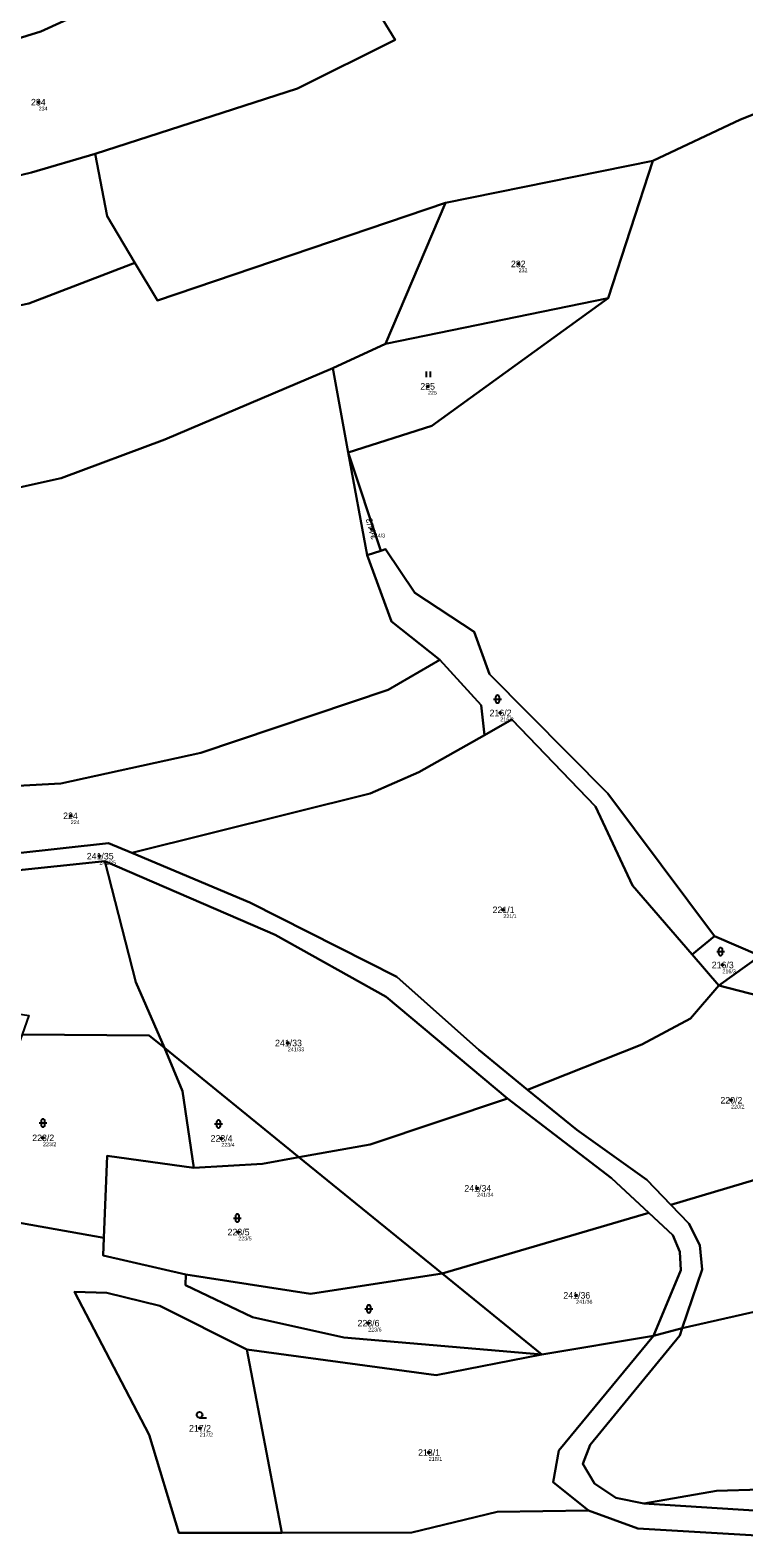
# Model space of a CAD drawing. Extents: x -766177 to -763254, y -1057727 to -1053915.
# Drawn here: x -764774.5 to -764589.7, y -1057477.4 to -1057086.8 of the extents above; entities that cross this region are included whole.
import ezdxf

# ---------------------------------------------------------------- set-up
doc = ezdxf.new("R2010")
doc.units = 0
for name, color, linetype in [('Vrstva 1', 7, 'Continuous'), ('Vrstva 2', 7, 'Continuous'), ('Vrstva 3', 7, 'Continuous'), ('Vrstva 50', 7, 'Continuous'), ('Vrstva 51', 7, 'Continuous')]:
    doc.layers.add(name, color=color, linetype=linetype)

msp = doc.modelspace()

# ---------------------------------------------------------------- linework, layer by layer
at = {"layer": 'Vrstva 1'}
for p, q in [((-764613.25, -1057120.65), (-764666.92, -1057131.53)), ((-764624.8, -1057156.25), (-764613.25, -1057120.65)), ((-764666.92, -1057131.53), (-764682.46, -1057168.07)), ((-764624.8, -1057156.25), (-764682.46, -1057168.07)), ((-764682.46, -1057168.07), (-764696.11, -1057174.39)), ((-764696.11, -1057174.39), (-764692.12, -1057196.22)), ((-764687.26, -1057222.81), (-764692.12, -1057196.22)), ((-764692.12, -1057196.22), (-764683.69, -1057221.69)), ((-764683.69, -1057221.69), (-764687.26, -1057222.81)), ((-764603.1, -1057326.29), (-764597.29, -1057321.56)), ((-764585.48, -1057326.67), (-764597.29, -1057321.56)), ((-764603.1, -1057326.29), (-764596.18, -1057334.33)), ((-764585.48, -1057326.67), (-764596.18, -1057334.33)), ((-764704.89, -1057378.8), (-764739.69, -1057350.49)), ((-764667.8, -1057408.98), (-764704.89, -1057378.8)), ((-764667.8, -1057408.98), (-764614.28, -1057393.22)), ((-764642.01, -1057429.97), (-764667.8, -1057408.98)), ((-764613.07, -1057425.08), (-764605.63, -1057423.15)), ((-764613.07, -1057425.08), (-764642.01, -1057429.97)), ((-764709.36, -1057476.11), (-764718.38, -1057428.64))]:
    msp.add_line(p, q, dxfattribs=at)
for points in [[(-764708.9, -1057047.43), (-764739.3, -1057069.37), (-764754.19, -1057078.72), (-764760.91, -1057082.25), (-764771.73, -1057087.14), (-764793.82, -1057093.95), (-764861.05, -1057109.51)], [(-764757.64, -1057118.88), (-764705.22, -1057101.91), (-764679.94, -1057089.32), (-764690.54, -1057072), (-764708.9, -1057047.43)], [(-764613.25, -1057120.65), (-764590.56, -1057109.9), (-764567.9, -1057100.88), (-764530.4, -1057087.58), (-764523, -1057086.68)], [(-764757.64, -1057118.88), (-764774.17, -1057123.68), (-764802.92, -1057130.57), (-764851.9, -1057136.58), (-764858.21, -1057124.08), (-764860.35, -1057113.34)], [(-764747.36, -1057147.07), (-764754.56, -1057134.97), (-764757.64, -1057118.88)], [(-764747.36, -1057147.07), (-764741.54, -1057156.84), (-764666.92, -1057131.53)], [(-764870.84, -1057163.2), (-764870.68, -1057169.13), (-764851.02, -1057169.28), (-764804.04, -1057163.72), (-764774.82, -1057157.64), (-764747.36, -1057147.07)], [(-764692.12, -1057196.22), (-764670.45, -1057189.31), (-764624.8, -1057156.25)], [(-764869.55, -1057216.04), (-764830.16, -1057214.01), (-764788.75, -1057207.77), (-764766.49, -1057202.85), (-764739.57, -1057192.87), (-764696.11, -1057174.39)], [(-764687.26, -1057222.81), (-764680.88, -1057240.01), (-764668.44, -1057249.98)], [(-764597.29, -1057321.56), (-764624.95, -1057284.61), (-764655.55, -1057253.65), (-764659.55, -1057242.65), (-764674.9, -1057232.59), (-764682.46, -1057221.3), (-764683.69, -1057221.69)], [(-764668.44, -1057249.98), (-764681.75, -1057257.76), (-764730.25, -1057274.03), (-764766.5, -1057282), (-764809.8, -1057284.32), (-764867.31, -1057280.02)], [(-764668.44, -1057249.98), (-764657.71, -1057261.73), (-764656.87, -1057269.44)], [(-764656.87, -1057269.44), (-764649.81, -1057265.44), (-764628.07, -1057287.93), (-764618.51, -1057308.39), (-764603.1, -1057326.29)], [(-764656.87, -1057269.44), (-764673.85, -1057279.08), (-764686.45, -1057284.59), (-764748.19, -1057299.95)], [(-764755.14, -1057302.1), (-764802.96, -1057307.13), (-764828.56, -1057306.85), (-764848.07, -1057303.89), (-764887.78, -1057292.31), (-764922.39, -1057276.56)], [(-764868.13, -1057292.61), (-764846.83, -1057298.86), (-764830.53, -1057302.17), (-764803.55, -1057302.86), (-764754.21, -1057297.42), (-764748.19, -1057299.95)], [(-764739.69, -1057350.49), (-764747.15, -1057333.46), (-764755.14, -1057302.1)], [(-764650.87, -1057363.57), (-764682.34, -1057337.25), (-764711.01, -1057321.23), (-764755.14, -1057302.1)], [(-764748.19, -1057299.95), (-764717.59, -1057312.78), (-764679.5, -1057332.08), (-764658.33, -1057351.01), (-764645.73, -1057361.34)], [(-764596.18, -1057334.33), (-764603.47, -1057342.88), (-764616.11, -1057349.59), (-764645.73, -1057361.34)], [(-764596.18, -1057334.33), (-764547.03, -1057347.02), (-764557.92, -1057373.65)], [(-764755.4, -1057399.73), (-764780.63, -1057395.22), (-764781.54, -1057404.07), (-764802.49, -1057376.7), (-764806.46, -1057378.71), (-764813.12, -1057370.35), (-764816.27, -1057358), (-764849.27, -1057346.5)], [(-764739.69, -1057350.49), (-764743.65, -1057347.27), (-764776.59, -1057347.03)], [(-764732.1, -1057381.53), (-764735, -1057361.74), (-764739.69, -1057350.49)], [(-764645.73, -1057361.34), (-764632.92, -1057371.7), (-764614.81, -1057384.71), (-764608.57, -1057391.19)], [(-764704.89, -1057378.8), (-764686.42, -1057375.49), (-764650.87, -1057363.57)], [(-764614.28, -1057393.22), (-764623.95, -1057384.26), (-764650.87, -1057363.57)], [(-764557.92, -1057373.65), (-764578.75, -1057382.25), (-764608.57, -1057391.19)], [(-764755.4, -1057399.73), (-764754.5, -1057378.44), (-764732.1, -1057381.53)], [(-764732.1, -1057381.53), (-764714.3, -1057380.49), (-764704.89, -1057378.8)], [(-764608.57, -1057391.19), (-764603.9, -1057396.03), (-764601.07, -1057401.62), (-764600.51, -1057407.95), (-764605.63, -1057423.15)], [(-764614.28, -1057393.22), (-764608.05, -1057398.99), (-764606.29, -1057403.35), (-764606.01, -1057408.11), (-764613.07, -1057425.08)], [(-764734.18, -1057409.2), (-764755.59, -1057404.26), (-764755.4, -1057399.73)], [(-764605.63, -1057423.15), (-764569.81, -1057415.01), (-764545.8, -1057406.28)], [(-764642.01, -1057429.97), (-764693.24, -1057425.5), (-764716.91, -1057420.27), (-764734.26, -1057411.97), (-764734.18, -1057409.2)], [(-764734.18, -1057409.2), (-764701.89, -1057414.24), (-764667.8, -1057408.98)], [(-764709.36, -1057476.11), (-764736, -1057476.13), (-764743.7, -1057450.78), (-764763, -1057413.7), (-764754.66, -1057413.92), (-764740.89, -1057417.34), (-764718.38, -1057428.64)], [(-764605.63, -1057423.15), (-764606.26, -1057425.04), (-764629.49, -1057453.31), (-764631.37, -1057458.3), (-764628.34, -1057463.35), (-764622.8, -1057467.04), (-764615.59, -1057468.57)], [(-764629.9, -1057470.32), (-764639.04, -1057463.01), (-764637.61, -1057454.84), (-764613.07, -1057425.08)], [(-764718.38, -1057428.64), (-764669.33, -1057435.27), (-764642.01, -1057429.97)], [(-764562.34, -1057464.26), (-764596.77, -1057465.25), (-764615.59, -1057468.57)], [(-764726.58, -1057546.1), (-764727.37, -1057543.39), (-764726.36, -1057541.28), (-764720.55, -1057536.37), (-764646.25, -1057513.93), (-764551.3, -1057486.98), (-764547.78, -1057481.46), (-764551.03, -1057478.94), (-764617.12, -1057475.05), (-764629.9, -1057470.32)], [(-764629.9, -1057470.32), (-764653.53, -1057470.72), (-764675.69, -1057476.08), (-764709.36, -1057476.11)], [(-764615.59, -1057468.57), (-764555.86, -1057472.34), (-764543.66, -1057472.33), (-764538.99, -1057474.65)]]:
    msp.add_lwpolyline(points, dxfattribs=at)
at = {"layer": 'Vrstva 3'}
for p, q in [((-764671.841, -1057176.73), (-764671.841, -1057175.23)), ((-764670.84, -1057176.73), (-764670.84, -1057175.23)), ((-764653.971, -1057259.611), (-764653.971, -1057260.612)), ((-764652.969, -1057260.612), (-764652.969, -1057259.611)), ((-764654.471, -1057260.111), (-764652.469, -1057260.111)), ((-764596.721, -1057325.551), (-764594.719, -1057325.551)), ((-764596.221, -1057325.051), (-764596.221, -1057326.052)), ((-764595.219, -1057326.052), (-764595.219, -1057325.051)), ((-764772.171, -1057369.951), (-764770.169, -1057369.951)), ((-764771.671, -1057369.451), (-764771.671, -1057370.452)), ((-764770.669, -1057370.452), (-764770.669, -1057369.451)), ((-764726.711, -1057370.211), (-764724.709, -1057370.211)), ((-764726.211, -1057369.711), (-764726.211, -1057370.712)), ((-764725.209, -1057370.712), (-764725.209, -1057369.711)), ((-764721.831, -1057394.571), (-764719.829, -1057394.571)), ((-764721.331, -1057394.071), (-764721.331, -1057395.072)), ((-764720.329, -1057395.072), (-764720.329, -1057394.071)), ((-764687.791, -1057418.131), (-764685.789, -1057418.131)), ((-764687.291, -1057417.631), (-764687.291, -1057418.632)), ((-764686.289, -1057418.632), (-764686.289, -1057417.631)), ((-764730.613, -1057446.32), (-764728.863, -1057446.32))]:
    msp.add_line(p, q, dxfattribs=at)
msp.add_circle((-764730.61286, -1057445.56981), 0.75, dxfattribs=at)
for centre, start, end in [((-764653.47, -1057259.6109), 0, 180), ((-764653.47, -1057260.6109), 180, 359.9878861), ((-764595.72, -1057325.0509), 0, 180), ((-764595.72, -1057326.0509), 180, 359.9878861), ((-764771.17, -1057369.4509), 0, 180), ((-764771.17, -1057370.4509), 180, 359.9878861), ((-764725.71, -1057369.7109), 0, 180), ((-764725.71, -1057370.7109), 180, 359.9878861), ((-764720.83, -1057394.0709), 0, 180), ((-764720.83, -1057395.0709), 180, 359.9878861), ((-764686.79, -1057417.6309), 0, 180), ((-764686.79, -1057418.6309), 180, 359.9878861)]:
    msp.add_arc(centre, 0.5, start, end, dxfattribs=at)
at = {"layer": 'Vrstva 50'}
for centre in [(-764772.29, -1057105.44994), (-764648.02, -1057147.35994), (-764671.49, -1057179.08994), (-764686.03, -1057216.08994), (-764652.75, -1057263.70994), (-764763.97, -1057290.35994), (-764756.51, -1057300.81994), (-764651.98, -1057314.71994), (-764595.23, -1057328.99994), (-764707.77, -1057349.21994), (-764592.99, -1057364.04994), (-764771.17, -1057373.79994), (-764724.99, -1057373.93994), (-764658.75, -1057386.87994), (-764720.59, -1057398.21994), (-764633.12, -1057414.60994), (-764686.95, -1057421.81994), (-764730.57, -1057449.04994), (-764671.27, -1057455.33994)]:
    msp.add_circle(centre, 0.25, dxfattribs=at)
at = {"layer": 'Vrstva 51'}
for points in [[(-764679.94, -1057089.32), (-764690.54, -1057072), (-764708.9, -1057047.43), (-764739.3, -1057069.37), (-764754.19, -1057078.72), (-764760.91, -1057082.25), (-764771.73, -1057087.14), (-764793.82, -1057093.95), (-764861.05, -1057109.51), (-764860.35, -1057113.34), (-764858.21, -1057124.08), (-764851.9, -1057136.58), (-764802.92, -1057130.57), (-764774.17, -1057123.68), (-764757.64, -1057118.88), (-764705.22, -1057101.91)], [(-764757.64, -1057118.88), (-764774.17, -1057123.68), (-764802.92, -1057130.57), (-764851.9, -1057136.58), (-764858.21, -1057124.08), (-764860.35, -1057113.34), (-764870.03, -1057115.78), (-764861.25, -1057137.73), (-764860.89, -1057161.89), (-764870.84, -1057163.2), (-764870.68, -1057169.13), (-764851.02, -1057169.28), (-764804.04, -1057163.72), (-764774.82, -1057157.64), (-764747.36, -1057147.07), (-764754.56, -1057134.97)], [(-764666.92, -1057131.53), (-764682.46, -1057168.07), (-764624.8, -1057156.25), (-764613.25, -1057120.65)], [(-764788.75, -1057207.77), (-764766.49, -1057202.85), (-764739.57, -1057192.87), (-764696.11, -1057174.39), (-764682.46, -1057168.07), (-764666.92, -1057131.53), (-764741.54, -1057156.84), (-764747.36, -1057147.07), (-764774.82, -1057157.64), (-764804.04, -1057163.72), (-764851.02, -1057169.28), (-764870.68, -1057169.13), (-764870.84, -1057163.2), (-764893.14, -1057162.06), (-764919.61, -1057158.38), (-764933.04, -1057198.39), (-764898.23, -1057209.6), (-764869.55, -1057216.04), (-764830.16, -1057214.01)], [(-764624.8, -1057156.25), (-764682.46, -1057168.07), (-764696.11, -1057174.39), (-764692.12, -1057196.22), (-764670.45, -1057189.31)], [(-764687.26, -1057222.81), (-764692.12, -1057196.22), (-764696.11, -1057174.39), (-764739.57, -1057192.87), (-764766.49, -1057202.85), (-764788.75, -1057207.77), (-764830.16, -1057214.01), (-764869.55, -1057216.04), (-764867.31, -1057280.02), (-764809.8, -1057284.32), (-764766.5, -1057282), (-764730.25, -1057274.03), (-764681.75, -1057257.76), (-764668.44, -1057249.98), (-764680.88, -1057240.01)], [(-764687.26, -1057222.81), (-764683.69, -1057221.69), (-764692.12, -1057196.22)], [(-764657.71, -1057261.73), (-764656.87, -1057269.44), (-764649.81, -1057265.44), (-764628.07, -1057287.93), (-764618.51, -1057308.39), (-764603.1, -1057326.29), (-764597.29, -1057321.56), (-764624.95, -1057284.61), (-764655.55, -1057253.65), (-764659.55, -1057242.65), (-764674.9, -1057232.59), (-764682.46, -1057221.3), (-764683.69, -1057221.69), (-764687.26, -1057222.81), (-764680.88, -1057240.01), (-764668.44, -1057249.98)], [(-764846.83, -1057298.86), (-764830.53, -1057302.17), (-764803.55, -1057302.86), (-764754.21, -1057297.42), (-764748.19, -1057299.95), (-764686.45, -1057284.59), (-764673.85, -1057279.08), (-764656.87, -1057269.44), (-764657.71, -1057261.73), (-764668.44, -1057249.98), (-764681.75, -1057257.76), (-764730.25, -1057274.03), (-764766.5, -1057282), (-764809.8, -1057284.32), (-764867.31, -1057280.02), (-764868.13, -1057292.61)], [(-764658.33, -1057351.01), (-764645.73, -1057361.34), (-764616.11, -1057349.59), (-764603.47, -1057342.88), (-764596.18, -1057334.33), (-764603.1, -1057326.29), (-764618.51, -1057308.39), (-764628.07, -1057287.93), (-764649.81, -1057265.44), (-764656.87, -1057269.44), (-764673.85, -1057279.08), (-764686.45, -1057284.59), (-764748.19, -1057299.95), (-764717.59, -1057312.78), (-764679.5, -1057332.08)], [(-764755.14, -1057302.1), (-764802.96, -1057307.13), (-764828.56, -1057306.85), (-764848.07, -1057303.89), (-764887.78, -1057292.31), (-764922.39, -1057276.56), (-764876.27, -1057330.63), (-764849.27, -1057346.5), (-764785.18, -1057346.97), (-764783.65, -1057340.72), (-764774.8, -1057342.1), (-764776.59, -1057347.03), (-764743.65, -1057347.27), (-764739.69, -1057350.49), (-764747.15, -1057333.46)], [(-764686.42, -1057375.49), (-764650.87, -1057363.57), (-764682.34, -1057337.25), (-764711.01, -1057321.23), (-764755.14, -1057302.1), (-764747.15, -1057333.46), (-764739.69, -1057350.49), (-764704.89, -1057378.8)], [(-764597.29, -1057321.56), (-764603.1, -1057326.29), (-764596.18, -1057334.33), (-764585.48, -1057326.67)], [(-764539.7, -1057377.9), (-764543.76, -1057363.76), (-764538.78, -1057345.35), (-764573.96, -1057331.45), (-764585.48, -1057326.67), (-764596.18, -1057334.33), (-764547.03, -1057347.02), (-764557.92, -1057373.65), (-764545.8, -1057406.28), (-764524.72, -1057439.08), (-764526.66, -1057449.51), (-764533.93, -1057457.05), (-764541.37, -1057462.32), (-764517.74, -1057455.1), (-764512.25, -1057445.44), (-764520.32, -1057414.8)], [(-764632.92, -1057371.7), (-764614.81, -1057384.71), (-764608.57, -1057391.19), (-764578.75, -1057382.25), (-764557.92, -1057373.65), (-764547.03, -1057347.02), (-764596.18, -1057334.33), (-764603.47, -1057342.88), (-764616.11, -1057349.59), (-764645.73, -1057361.34)], [(-764732.1, -1057381.53), (-764735, -1057361.74), (-764739.69, -1057350.49), (-764743.65, -1057347.27), (-764776.59, -1057347.03), (-764786.38, -1057374.02), (-764791.71, -1057373.58), (-764785.18, -1057346.97), (-764849.27, -1057346.5), (-764816.27, -1057358), (-764813.12, -1057370.35), (-764806.46, -1057378.71), (-764802.49, -1057376.7), (-764781.54, -1057404.07), (-764780.63, -1057395.22), (-764755.4, -1057399.73), (-764754.5, -1057378.44)], [(-764714.3, -1057380.49), (-764704.89, -1057378.8), (-764739.69, -1057350.49), (-764735, -1057361.74), (-764732.1, -1057381.53)], [(-764667.8, -1057408.98), (-764614.28, -1057393.22), (-764623.95, -1057384.26), (-764650.87, -1057363.57), (-764686.42, -1057375.49), (-764704.89, -1057378.8)], [(-764569.81, -1057415.01), (-764545.8, -1057406.28), (-764557.92, -1057373.65), (-764578.75, -1057382.25), (-764608.57, -1057391.19), (-764603.9, -1057396.03), (-764601.07, -1057401.62), (-764600.51, -1057407.95), (-764605.63, -1057423.15)], [(-764704.89, -1057378.8), (-764714.3, -1057380.49), (-764732.1, -1057381.53), (-764754.5, -1057378.44), (-764755.4, -1057399.73), (-764755.59, -1057404.26), (-764734.18, -1057409.2), (-764701.89, -1057414.24), (-764667.8, -1057408.98)], [(-764642.01, -1057429.97), (-764613.07, -1057425.08), (-764606.01, -1057408.11), (-764606.29, -1057403.35), (-764608.05, -1057398.99), (-764614.28, -1057393.22), (-764667.8, -1057408.98)], [(-764606.26, -1057425.04), (-764629.49, -1057453.31), (-764631.37, -1057458.3), (-764628.34, -1057463.35), (-764622.8, -1057467.04), (-764615.59, -1057468.57), (-764596.77, -1057465.25), (-764562.34, -1057464.26), (-764554.07, -1057464.03), (-764541.37, -1057462.32), (-764533.93, -1057457.05), (-764526.66, -1057449.51), (-764524.72, -1057439.08), (-764545.8, -1057406.28), (-764569.81, -1057415.01), (-764605.63, -1057423.15)], [(-764667.8, -1057408.98), (-764701.89, -1057414.24), (-764734.18, -1057409.2), (-764734.26, -1057411.97), (-764716.91, -1057420.27), (-764693.24, -1057425.5), (-764642.01, -1057429.97)], [(-764709.36, -1057476.11), (-764718.38, -1057428.64), (-764740.89, -1057417.34), (-764754.66, -1057413.92), (-764763, -1057413.7), (-764743.7, -1057450.78), (-764736, -1057476.13)], [(-764613.07, -1057425.08), (-764642.01, -1057429.97), (-764669.33, -1057435.27), (-764718.38, -1057428.64), (-764709.36, -1057476.11), (-764675.69, -1057476.08), (-764653.53, -1057470.72), (-764629.9, -1057470.32), (-764639.04, -1057463.01), (-764637.61, -1057454.84)], [(-764555.86, -1057472.34), (-764543.66, -1057472.33), (-764538.99, -1057474.65), (-764541.37, -1057462.32), (-764554.07, -1057464.03), (-764553.53, -1057470.15), (-764561.76, -1057470.88), (-764561.85, -1057469.78), (-764563.65, -1057469.94), (-764563.74, -1057468.84), (-764565.34, -1057468.98), (-764565.55, -1057466.59), (-764562.17, -1057466.27), (-764562.3, -1057464.76), (-764562.34, -1057464.26), (-764596.77, -1057465.25), (-764615.59, -1057468.57)]]:
    msp.add_lwpolyline(points, close=True, dxfattribs=at)
for points in [[(-764690.54, -1057072), (-764679.94, -1057089.32), (-764705.22, -1057101.91), (-764757.64, -1057118.88), (-764754.56, -1057134.97), (-764747.36, -1057147.07), (-764741.54, -1057156.84), (-764666.92, -1057131.53), (-764613.25, -1057120.65), (-764590.56, -1057109.9), (-764567.9, -1057100.88), (-764530.4, -1057087.58), (-764523, -1057086.68)], [(-765120.92, -1057105.49), (-765132.06, -1057104.64), (-765144.61, -1057099.5), (-765119.62, -1057116.57), (-765110.97, -1057106.23), (-765101.85, -1057099.67), (-765095.59, -1057097.01), (-765080.3, -1057092.52), (-765037.34, -1057100.66), (-764983.43, -1057111.42), (-764945.64, -1057115.02), (-764932.54, -1057114.72), (-764920.57, -1057114.44), (-764904.74, -1057114.07), (-764880.78, -1057113.51), (-764861.05, -1057109.51), (-764793.82, -1057093.95), (-764771.73, -1057087.14), (-764760.91, -1057082.25)], [(-764567.9, -1057100.88), (-764590.56, -1057109.9), (-764613.25, -1057120.65), (-764624.8, -1057156.25), (-764670.45, -1057189.31), (-764692.12, -1057196.22), (-764683.69, -1057221.69), (-764682.46, -1057221.3), (-764674.9, -1057232.59), (-764659.55, -1057242.65), (-764655.55, -1057253.65), (-764624.95, -1057284.61), (-764597.29, -1057321.56), (-764585.48, -1057326.67)], [(-764802.96, -1057307.13), (-764755.14, -1057302.1), (-764711.01, -1057321.23), (-764682.34, -1057337.25), (-764650.87, -1057363.57), (-764623.95, -1057384.26), (-764614.28, -1057393.22), (-764608.05, -1057398.99), (-764606.29, -1057403.35), (-764606.01, -1057408.11), (-764613.07, -1057425.08), (-764605.63, -1057423.15), (-764600.51, -1057407.95), (-764601.07, -1057401.62), (-764603.9, -1057396.03), (-764608.57, -1057391.19), (-764614.81, -1057384.71), (-764632.92, -1057371.7), (-764645.73, -1057361.34), (-764658.33, -1057351.01), (-764679.5, -1057332.08), (-764717.59, -1057312.78), (-764748.19, -1057299.95), (-764754.21, -1057297.42), (-764803.55, -1057302.86)], [(-764551.03, -1057478.94), (-764617.12, -1057475.05), (-764629.9, -1057470.32), (-764653.53, -1057470.72), (-764675.69, -1057476.08), (-764709.36, -1057476.11), (-764736, -1057476.13), (-764743.7, -1057450.78), (-764763, -1057413.7), (-764754.66, -1057413.92), (-764740.89, -1057417.34), (-764718.38, -1057428.64), (-764669.33, -1057435.27), (-764642.01, -1057429.97), (-764693.24, -1057425.5), (-764716.91, -1057420.27), (-764734.26, -1057411.97), (-764734.18, -1057409.2), (-764755.59, -1057404.26), (-764755.4, -1057399.73), (-764780.63, -1057395.22)], [(-764555.86, -1057472.34), (-764615.59, -1057468.57), (-764622.8, -1057467.04), (-764628.34, -1057463.35), (-764631.37, -1057458.3), (-764629.49, -1057453.31), (-764606.26, -1057425.04), (-764605.63, -1057423.15), (-764613.07, -1057425.08), (-764637.61, -1057454.84), (-764639.04, -1057463.01), (-764629.9, -1057470.32), (-764617.12, -1057475.05), (-764551.03, -1057478.94)]]:
    msp.add_lwpolyline(points, dxfattribs=at)

# ---------------------------------------------------------------- texts
at = {"layer": 'Vrstva 2'}
for s, p in [('234', (-764774.264, -1057106.3)), ('232', (-764649.994, -1057148.21)), ('225', (-764673.464, -1057179.94)), ('216/2', (-764655.523, -1057264.56)), ('224', (-764765.944, -1057291.21)), ('241/35', (-764759.815, -1057301.67)), ('221/1', (-764654.753, -1057315.57)), ('216/3', (-764598.003, -1057329.85)), ('241/33', (-764711.075, -1057350.07)), ('220/2', (-764595.763, -1057364.9)), ('223/2', (-764773.943, -1057374.65)), ('223/4', (-764727.763, -1057374.79)), ('241/34', (-764662.055, -1057387.73)), ('223/5', (-764723.363, -1057399.07)), ('241/36', (-764636.425, -1057415.46)), ('223/6', (-764689.723, -1057422.67)), ('217/2', (-764733.343, -1057449.9)), ('218/1', (-764674.043, -1057456.19))]:
    msp.add_text(s, height=1.699998, dxfattribs=at).set_placement(p)
msp.add_text('244/3', height=1.699998, rotation=106, dxfattribs=at).set_placement((-764684.448, -1057218.521))
at = {"layer": 'Vrstva 50'}
for s, p in [('234', (-764772.29, -1057107.606)), ('232', (-764648.02, -1057149.516)), ('225', (-764671.49, -1057181.246)), ('244/3', (-764686.03, -1057218.246)), ('216/2', (-764652.75, -1057265.866)), ('224', (-764763.97, -1057292.516)), ('241/35', (-764756.51, -1057302.976)), ('221/1', (-764651.98, -1057316.876)), ('216/3', (-764595.23, -1057331.156)), ('241/33', (-764707.77, -1057351.376)), ('220/2', (-764592.99, -1057366.206)), ('223/2', (-764771.17, -1057375.956)), ('223/4', (-764724.99, -1057376.096)), ('241/34', (-764658.75, -1057389.036)), ('223/5', (-764720.59, -1057400.376)), ('241/36', (-764633.12, -1057416.766)), ('223/6', (-764686.95, -1057423.976)), ('217/2', (-764730.57, -1057451.206)), ('218/1', (-764671.27, -1057457.496))]:
    msp.add_text(s, height=0.999996, dxfattribs=at).set_placement(p)

doc.saveas('drawing.dxf')
